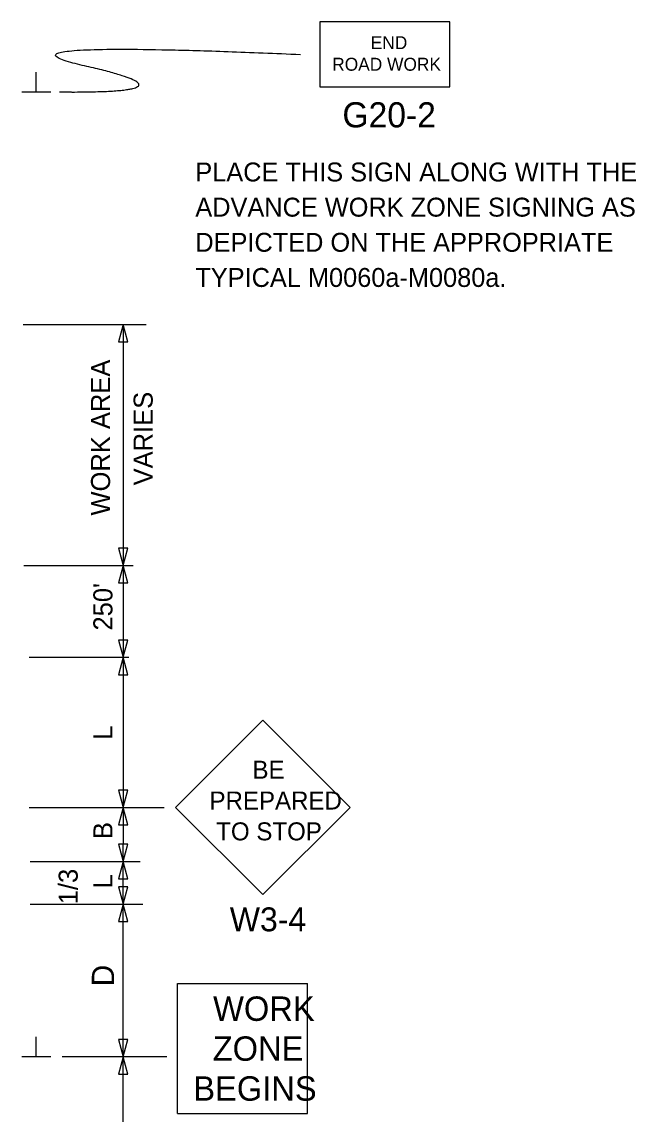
# Model space of a CAD drawing. Extents: x -1809 to 1554, y -1087 to 323.
# Drawn here: x -1392.2 to -1165.1, y -403.2 to 0.7 of the extents above; entities that cross this region are included whole.
import ezdxf

# ---------------------------------------------------------------- set-up
doc = ezdxf.new("R2010")
doc.units = 0
for name, color, linetype in [('PAVT_EDGE_PR', 7, 'Continuous'), ('TRAFFIC_SIGNS_PR', 7, 'Continuous'), ('TYPICAL_EX', 7, 'Continuous'), ('TYPICAL_TEXT_DIMEN_PR', 7, 'Continuous')]:
    doc.layers.add(name, color=color, linetype=linetype)

msp = doc.modelspace()

# ---------------------------------------------------------------- linework, layer by layer
at = {"layer": 'PAVT_EDGE_PR'}
msp.add_line((-1373.78, -25.26), (-1378.26, -25.26), dxfattribs=at)
at = {"layer": 'TRAFFIC_SIGNS_PR'}
for p, q in [((-1303.11, -257.54), (-1335.35, -289.78)), ((-1270.87, -289.78), (-1303.11, -257.54)), ((-1335.35, -289.78), (-1303.11, -322.02)), ((-1303.11, -322.02), (-1270.87, -289.78)), ((-1334.64, -402.93), (-1334.64, -354.93)), ((-1334.64, -354.93), (-1286.64, -354.93)), ((-1286.64, -402.93), (-1286.64, -354.93)), ((-1334.64, -402.93), (-1286.64, -402.93))]:
    msp.add_line(p, q, dxfattribs=at)
msp.add_lwpolyline([(-1281.98, -23.3), (-1233.98, -23.3), (-1233.98, 0.7), (-1281.98, 0.7)], close=True, dxfattribs=at)
at = {"layer": 'TYPICAL_EX'}
for p, q in [((-1386.83, -25.35), (-1386.83, -17.95)), ((-1386.83, -25.35), (-1392.17, -25.35)), ((-1381.48, -25.35), (-1386.83, -25.35)), ((-1386.83, -382.02), (-1386.83, -374.63)), ((-1386.83, -382.02), (-1392.17, -382.02)), ((-1381.48, -382.02), (-1386.83, -382.02))]:
    msp.add_line(p, q, dxfattribs=at)
at = {"layer": 'TYPICAL_TEXT_DIMEN_PR'}
for p, q in [((-1391.63, -111.25), (-1346.17, -111.25)), ((-1354.71, -111.25), (-1356.4, -117.65)), ((-1353.01, -117.65), (-1354.71, -111.25)), ((-1354.71, -111.29), (-1354.71, -303.33)), ((-1356.4, -117.65), (-1354.71, -117.65)), ((-1354.71, -117.65), (-1353.01, -117.65)), ((-1354.71, -193.88), (-1356.4, -193.88)), ((-1356.4, -193.88), (-1354.71, -200.29)), ((-1354.71, -200.29), (-1353.01, -193.88)), ((-1353.01, -193.88), (-1354.71, -193.88)), ((-1391.47, -200.29), (-1351.05, -200.29)), ((-1354.71, -200.29), (-1356.4, -206.69)), ((-1353.01, -206.69), (-1354.71, -200.29)), ((-1356.4, -206.69), (-1354.71, -206.69)), ((-1354.71, -206.69), (-1353.01, -206.69)), ((-1354.71, -227.9), (-1356.4, -227.9)), ((-1356.4, -227.9), (-1354.71, -234.3)), ((-1354.71, -234.3), (-1353.01, -227.9)), ((-1353.01, -227.9), (-1354.71, -227.9)), ((-1389.41, -234.3), (-1352.67, -234.3)), ((-1354.71, -234.3), (-1356.4, -240.71)), ((-1353.01, -240.71), (-1354.71, -234.3)), ((-1356.4, -240.71), (-1354.71, -240.71)), ((-1354.71, -240.71), (-1353.01, -240.71)), ((-1354.71, -283.37), (-1356.4, -283.37)), ((-1356.4, -283.37), (-1354.71, -289.77)), ((-1354.71, -289.77), (-1353.01, -283.37)), ((-1353.01, -283.37), (-1354.71, -283.37)), ((-1389.41, -289.78), (-1339.61, -289.78)), ((-1354.71, -289.77), (-1356.4, -296.18)), ((-1353.01, -296.18), (-1354.71, -289.77)), ((-1356.4, -296.18), (-1354.71, -296.18)), ((-1354.71, -296.18), (-1353.01, -296.18)), ((-1354.72, -303.39), (-1356.42, -303.39)), ((-1356.42, -303.39), (-1354.72, -309.8)), ((-1354.72, -309.8), (-1353.03, -303.39)), ((-1353.03, -303.39), (-1354.72, -303.39)), ((-1354.72, -325.38), (-1354.72, -303.48)), ((-1389.14, -309.8), (-1348.42, -309.8)), ((-1354.72, -309.8), (-1356.42, -316.2)), ((-1353.03, -316.2), (-1354.72, -309.8)), ((-1356.42, -316.2), (-1354.72, -316.2)), ((-1354.72, -316.2), (-1353.03, -316.2)), ((-1354.72, -319.13), (-1356.42, -319.13)), ((-1356.42, -319.13), (-1354.72, -325.54)), ((-1354.72, -325.54), (-1353.03, -319.13)), ((-1353.03, -319.13), (-1354.72, -319.13)), ((-1389.14, -325.54), (-1347.5, -325.54)), ((-1354.72, -325.54), (-1356.42, -331.94)), ((-1354.72, -382.13), (-1354.72, -325.38)), ((-1353.03, -331.94), (-1354.72, -325.54)), ((-1356.42, -331.94), (-1354.72, -331.94)), ((-1354.72, -331.94), (-1353.03, -331.94)), ((-1354.72, -375.58), (-1356.42, -375.58)), ((-1356.42, -375.58), (-1354.72, -381.99)), ((-1354.72, -381.99), (-1353.03, -375.58)), ((-1353.03, -375.58), (-1354.72, -375.58)), ((-1338.58, -381.99), (-1377.28, -381.99)), ((-1354.72, -381.99), (-1356.42, -388.39)), ((-1353.03, -388.39), (-1354.72, -381.99)), ((-1354.72, -438.17), (-1354.72, -382.13)), ((-1356.42, -388.39), (-1354.72, -388.39)), ((-1354.72, -388.39), (-1353.03, -388.39))]:
    msp.add_line(p, q, dxfattribs=at)
msp.add_open_spline([(-1373.73, -25.25), (-1326.6, -25.25), (-1411.13, -5.99), (-1289.24, -11.35)], degree=2, dxfattribs=at)

# ---------------------------------------------------------------- texts
at = {"layer": 'TRAFFIC_SIGNS_PR'}
for s, height, p in [('END', 4.789, (-1263.23, -9.39)), ('ROAD WORK', 4.789, (-1277.47, -17.38)), ('G20-2', 9.3, (-1273.7, -38.33)), ('PLACE THIS SIGN ALONG WITH THE', 7, (-1328.05, -58.33)), ('ADVANCE WORK ZONE SIGNING AS', 7, (-1328.05, -71.33)), ('DEPICTED ON THE APPROPRIATE', 7, (-1328.05, -84.33)), ('TYPICAL M0060a-M0080a.', 7, (-1328.05, -97.33)), ('BE', 6.65, (-1306.93, -279.18)), ('PREPARED', 6.65, (-1322.81, -290.58)), ('TO STOP', 6.65, (-1320.33, -301.98)), ('W3-4', 8.835, (-1315.31, -335.61)), ('WORK', 9.021, (-1321.49, -368.73)), ('ZONE', 9.021, (-1321.64, -383.49)), ('BEGINS', 9.021, (-1328.8, -398.25))]:
    msp.add_text(s, height=height, dxfattribs=at).set_placement(p)
at = {"layer": 'TYPICAL_TEXT_DIMEN_PR'}
for s, height, p in [('WORK AREA', 7.054, (-1359.56, -181.86)), ('VARIES', 7.054, (-1343.8, -170.71)), ("250'", 7.054, (-1358.69, -224.38)), ('L', 7.05, (-1358.69, -264.77)), ('B', 7.05, (-1358.69, -301.48)), ('1/3', 7.054, (-1371.52, -325.61)), ('L', 7.05, (-1358.69, -319.73)), ('D', 8.25, (-1358.09, -355.96))]:
    msp.add_text(s, height=height, rotation=90, dxfattribs=at).set_placement(p)

doc.saveas('drawing.dxf')
